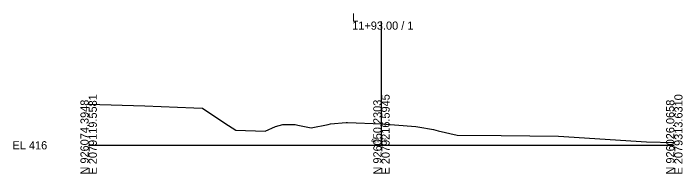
# Model space of a CAD drawing. Extents: x -26 to 10503, y -10 to 9546.
# Drawn here: x 2174.3 to 2402.8, y -9.7 to 45.1 of the extents above; entities that cross this region are included whole.
import ezdxf

# ---------------------------------------------------------------- set-up
doc = ezdxf.new("R2010")
doc.units = 0
for name, color, linetype in [('Exist Cross Section Cell', 7, 'Continuous'), ('Exist XS Center Line Elevation Label', 7, 'Continuous'), ('Exist XS Ground Line', 7, 'Continuous')]:
    doc.layers.add(name, color=color, linetype=linetype)

msp = doc.modelspace()

# ---------------------------------------------------------------- linework, layer by layer
at = {"layer": 'Exist Cross Section Cell'}
for p, q in [((2300, 0), (2300, 42.35)), ((2200, 0), (2300, 0)), ((2300, 0), (2400, 0))]:
    msp.add_line(p, q, dxfattribs=at)
at = {"layer": 'Exist XS Ground Line'}
for p, q in [((2200, 14.12), (2219.15, 13.55)), ((2219.15, 13.55), (2235.97, 12.81)), ((2235.97, 12.81), (2238.9, 12.69)), ((2238.9, 12.69), (2246.5, 7.62)), ((2246.5, 7.62), (2250.24, 5.2)), ((2263.85, 6.48), (2266.3, 7.12)), ((2266.3, 7.12), (2267.9, 7.17)), ((2267.9, 7.17), (2269.4, 7.15)), ((2269.4, 7.15), (2270.58, 7.13)), ((2270.58, 7.13), (2271.4, 6.92)), ((2271.4, 6.92), (2276.04, 5.97)), ((2276.04, 5.97), (2281.76, 7.12)), ((2281.76, 7.12), (2282.63, 7.3)), ((2282.63, 7.3), (2287.98, 7.79)), ((2287.98, 7.79), (2288.4, 7.82)), ((2288.4, 7.82), (2300.13, 7.39)), ((2300.13, 7.39), (2310.27, 6.58)), ((2250.24, 5.2), (2260.31, 4.86)), ((2260.31, 4.86), (2263.85, 6.48)), ((2310.27, 6.58), (2311.76, 6.44)), ((2311.76, 6.44), (2312.43, 6.32)), ((2312.43, 6.32), (2317.79, 5.36)), ((2317.79, 5.36), (2319.37, 4.97)), ((2319.37, 4.97), (2325.85, 3.46)), ((2325.85, 3.46), (2340.83, 3.4)), ((2340.83, 3.4), (2360.48, 3.08)), ((2360.48, 3.08), (2390.49, 1.2)), ((2390.49, 1.2), (2400, 0.99))]:
    msp.add_line(p, q, dxfattribs=at)

# ---------------------------------------------------------------- texts
at = {"layer": 'Exist Cross Section Cell'}
for s, p in [('L', (2290, 42.35)), ('11+93.00 / 1', (2290, 39.55)), ('EL 416', (2174, -1.4))]:
    msp.add_text(s, height=2.8, dxfattribs=at).set_placement(p)
for s, p in [('E 2079119.5581', (2202.8, -10)), ('E 2079216.5945', (2302.8, -10)), ('E 2079313.6310', (2402.8, -10)), ('N 926074.3948', (2200, -10)), ('N 926050.2303', (2300, -10)), ('N 926026.0658', (2400, -10))]:
    msp.add_text(s, height=2.8, rotation=90, dxfattribs=at).set_placement(p)
at = {"layer": 'Exist XS Center Line Elevation Label'}
msp.add_text('423.40', height=1.25, rotation=360, dxfattribs=at).set_placement((2296.44, 1.07))

doc.saveas('drawing.dxf')
